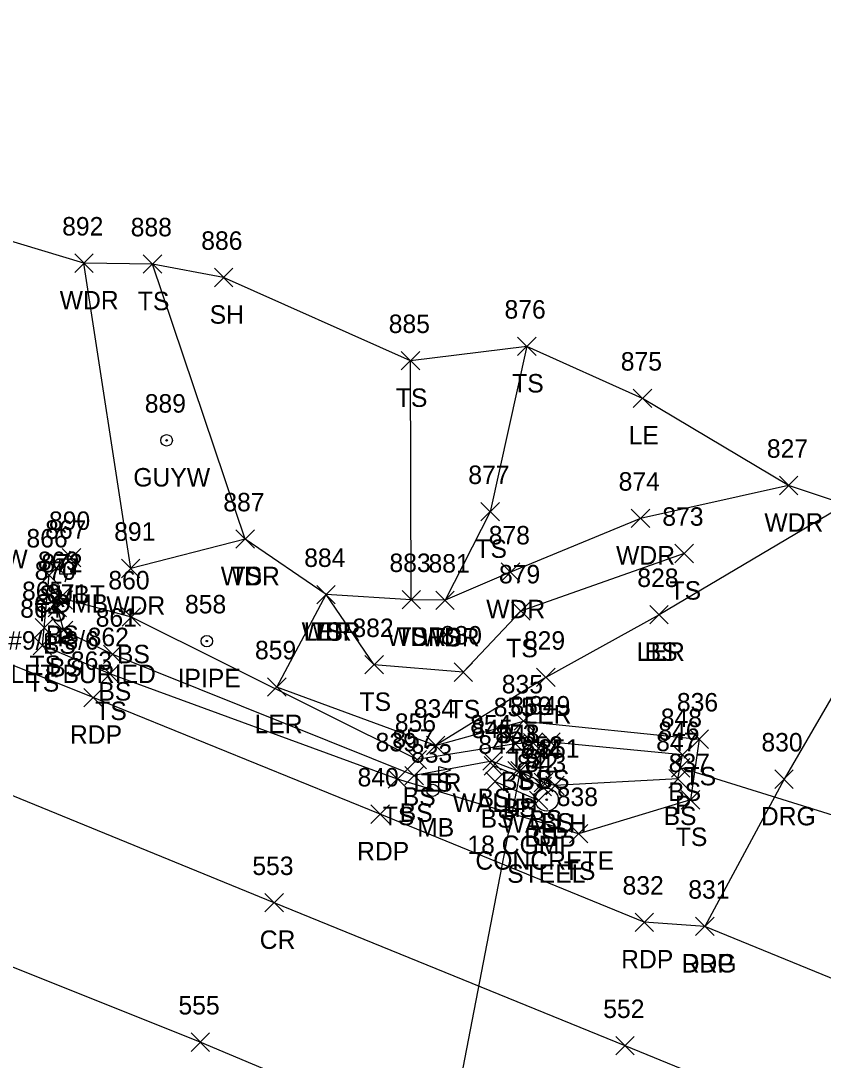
# Model space of a CAD drawing. Extents: x 1599569 to 1610055, y 642560 to 647860.
# Drawn here: x 1603043.9 to 1603130.8, y 647336.2 to 647448.7 of the extents above; entities that cross this region are included whole.
import ezdxf

# ---------------------------------------------------------------- set-up
doc = ezdxf.new("R2010")
doc.units = 0
for name, color, linetype in [('D_A', 7, 'Continuous'), ('D_C', 7, 'Continuous'), ('D_I', 7, 'Continuous'), ('D_TIC', 7, 'Continuous'), ('DCP', 7, 'Continuous'), ('DHW', 7, 'Continuous'), ('L_A', 7, 'Continuous'), ('L_I', 7, 'Continuous'), ('L_TIC', 7, 'Continuous'), ('LARO', 7, 'Continuous'), ('LAWA', 7, 'Continuous'), ('LELB', 7, 'Continuous'), ('LMB', 7, 'Continuous'), ('LSOGP', 7, 'Continuous'), ('M_A', 7, 'Continuous'), ('M_I', 7, 'Continuous'), ('MPIP', 7, 'Continuous'), ('P_A', 7, 'Continuous'), ('P_I', 7, 'Continuous'), ('P_TIC', 7, 'Continuous'), ('PET', 7, 'Continuous'), ('PRC', 7, 'Continuous'), ('R_A', 7, 'Continuous'), ('R_C', 7, 'Continuous'), ('R_I', 7, 'Continuous'), ('R_TIC', 7, 'Continuous'), ('RDG', 7, 'Continuous'), ('RGP', 7, 'Continuous'), ('U_A', 7, 'Continuous'), ('U_C', 7, 'Continuous'), ('U_I', 7, 'Continuous'), ('U_TIC', 7, 'Continuous'), ('UP', 7, 'Continuous'), ('UPGW', 7, 'Continuous')]:
    doc.layers.add(name, color=color, linetype=linetype)

msp = doc.modelspace()

# ---------------------------------------------------------------- linework, layer by layer
at = {"layer": 'D_TIC'}
for points in [[(1603047.45, 647385.01), (1603049.45, 647387.01)], [(1603049.45, 647385.01), (1603047.45, 647387.01)], [(1603094.04, 647367.06), (1603096.04, 647369.06)], [(1603096.04, 647367.06), (1603094.04, 647369.06)], [(1603114.32, 647366.84), (1603116.32, 647368.84)], [(1603116.32, 647366.84), (1603114.32, 647368.84)], [(1603096.94, 647366.51), (1603098.94, 647368.51)], [(1603098.94, 647366.51), (1603096.94, 647368.51)], [(1603099.35, 647364.81), (1603101.35, 647366.81)], [(1603101.35, 647364.81), (1603099.35, 647366.81)]]:
    msp.add_lwpolyline(points, dxfattribs=at)
at = {"layer": 'DCP'}
for points in [[(1603145.08, 647358.57), (1603115.32, 647367.84)], [(1603097.94, 647367.51), (1603085.93, 647305.24)]]:
    msp.add_lwpolyline(points, dxfattribs=at)
at = {"layer": 'DHW'}
msp.add_lwpolyline([(1603100.35, 647365.81), (1603095.04, 647368.06)], dxfattribs=at)
at = {"layer": 'L_TIC'}
for points in [[(1603049.71, 647421.48), (1603051.71, 647423.48)], [(1603051.71, 647421.48), (1603049.71, 647423.48)], [(1603057.13, 647421.39), (1603059.13, 647423.39)], [(1603059.13, 647421.39), (1603057.13, 647423.39)], [(1603064.83, 647419.93), (1603066.83, 647421.93)], [(1603066.83, 647419.93), (1603064.83, 647421.93)], [(1603097.67, 647412.48), (1603099.67, 647414.48)], [(1603099.67, 647412.48), (1603097.67, 647414.48)], [(1603085.07, 647410.92), (1603087.07, 647412.92)], [(1603087.07, 647410.92), (1603085.07, 647412.92)], [(1603110.2, 647406.85), (1603112.2, 647408.85)], [(1603112.2, 647406.85), (1603110.2, 647408.85)], [(1603126.02, 647397.41), (1603128.02, 647399.41)], [(1603128.02, 647397.41), (1603126.02, 647399.41)], [(1603093.69, 647394.57), (1603095.69, 647396.57)], [(1603095.69, 647394.57), (1603093.69, 647396.57)], [(1603109.97, 647393.85), (1603111.97, 647395.85)], [(1603111.97, 647393.85), (1603109.97, 647395.85)], [(1603067.17, 647391.61), (1603069.17, 647393.61)], [(1603069.17, 647391.61), (1603067.17, 647393.61)], [(1603067.17, 647391.61), (1603069.17, 647393.61)], [(1603069.17, 647391.61), (1603067.17, 647393.61)], [(1603114.71, 647390.05), (1603116.71, 647392.05)], [(1603116.71, 647390.05), (1603114.71, 647392.05)], [(1603054.77, 647388.42), (1603056.77, 647390.42)], [(1603056.77, 647388.42), (1603054.77, 647390.42)], [(1603045.94, 647387.7), (1603047.94, 647389.7)], [(1603047.94, 647387.7), (1603045.94, 647389.7)], [(1603095.9, 647388.03), (1603097.9, 647390.03)], [(1603097.9, 647388.03), (1603095.9, 647390.03)], [(1603047.14, 647385.25), (1603049.14, 647387.25)], [(1603049.14, 647385.25), (1603047.14, 647387.25)], [(1603075.92, 647385.59), (1603077.92, 647387.59)], [(1603077.92, 647385.59), (1603075.92, 647387.59)], [(1603075.92, 647385.59), (1603077.92, 647387.59)], [(1603077.92, 647385.59), (1603075.92, 647387.59)], [(1603075.92, 647385.59), (1603077.92, 647387.59)], [(1603077.92, 647385.59), (1603075.92, 647387.59)], [(1603085.15, 647385.04), (1603087.15, 647387.04)], [(1603087.15, 647385.04), (1603085.15, 647387.04)], [(1603085.15, 647385.04), (1603087.15, 647387.04)], [(1603087.15, 647385.04), (1603085.15, 647387.04)], [(1603088.81, 647384.98), (1603090.81, 647386.98)], [(1603090.81, 647384.98), (1603088.81, 647386.98)], [(1603088.81, 647384.98), (1603090.81, 647386.98)], [(1603090.81, 647384.98), (1603088.81, 647386.98)], [(1603046.82, 647384.19), (1603048.82, 647386.19)], [(1603048.82, 647384.19), (1603046.82, 647386.19)], [(1603097.02, 647383.81), (1603099.02, 647385.81)], [(1603099.02, 647383.81), (1603097.02, 647385.81)], [(1603054.84, 647383.16), (1603056.84, 647385.16)], [(1603056.84, 647383.16), (1603054.84, 647385.16)], [(1603111.99, 647383.42), (1603113.99, 647385.42)], [(1603113.99, 647383.42), (1603111.99, 647385.42)], [(1603111.99, 647383.42), (1603113.99, 647385.42)], [(1603113.99, 647383.42), (1603111.99, 647385.42)], [(1603045.41, 647382), (1603047.41, 647384)], [(1603047.41, 647382), (1603045.41, 647384)], [(1603047.5, 647381.72), (1603049.5, 647383.72)], [(1603049.5, 647381.72), (1603047.5, 647383.72)], [(1603047.5, 647381.72), (1603049.5, 647383.72)], [(1603049.5, 647381.72), (1603047.5, 647383.72)], [(1603045.21, 647380.09), (1603047.21, 647382.09)], [(1603047.21, 647380.09), (1603045.21, 647382.09)], [(1603052.82, 647379.12), (1603054.82, 647381.12)], [(1603054.82, 647379.12), (1603052.82, 647381.12)], [(1603081.14, 647378), (1603083.14, 647380)], [(1603083.14, 647378), (1603081.14, 647380)], [(1603052.52, 647377.01), (1603054.52, 647379.01)], [(1603054.52, 647377.01), (1603052.52, 647379.01)], [(1603090.79, 647377.19), (1603092.79, 647379.19)], [(1603092.79, 647377.19), (1603090.79, 647379.19)], [(1603099.72, 647376.63), (1603101.72, 647378.63)], [(1603101.72, 647376.63), (1603099.72, 647378.63)], [(1603070.6, 647375.59), (1603072.6, 647377.59)], [(1603072.6, 647375.59), (1603070.6, 647377.59)], [(1603097.31, 647371.9), (1603099.31, 647373.9)], [(1603099.31, 647371.9), (1603097.31, 647373.9)], [(1603087.79, 647369.26), (1603089.79, 647371.26)], [(1603089.79, 647369.26), (1603087.79, 647371.26)], [(1603087.79, 647369.26), (1603089.79, 647371.26)], [(1603089.79, 647369.26), (1603087.79, 647371.26)], [(1603096.44, 647369.42), (1603098.44, 647371.42)], [(1603098.44, 647369.42), (1603096.44, 647371.42)], [(1603098.32, 647369.56), (1603100.32, 647371.56)], [(1603100.32, 647369.56), (1603098.32, 647371.56)], [(1603100.28, 647369.61), (1603102.28, 647371.61)], [(1603102.28, 647369.61), (1603100.28, 647371.61)], [(1603116.34, 647369.94), (1603118.34, 647371.94)], [(1603118.34, 647369.94), (1603116.34, 647371.94)], [(1603114.53, 647368.25), (1603116.53, 647370.25)], [(1603116.53, 647368.25), (1603114.53, 647370.25)], [(1603085.79, 647367.73), (1603087.79, 647369.73)], [(1603087.79, 647367.73), (1603085.79, 647369.73)], [(1603093.89, 647367.57), (1603095.89, 647369.57)], [(1603095.89, 647367.57), (1603093.89, 647369.57)], [(1603083.66, 647365.62), (1603085.66, 647367.62)], [(1603085.66, 647365.62), (1603083.66, 647367.62)], [(1603085.46, 647365.99), (1603087.46, 647367.99)], [(1603087.46, 647365.99), (1603085.46, 647367.99)], [(1603096.61, 647366.53), (1603098.61, 647368.53)], [(1603098.61, 647366.53), (1603096.61, 647368.53)], [(1603114.03, 647365.64), (1603116.03, 647367.64)], [(1603116.03, 647365.64), (1603114.03, 647367.64)], [(1603114.03, 647365.64), (1603116.03, 647367.64)], [(1603116.03, 647365.64), (1603114.03, 647367.64)], [(1603094.22, 647365.36), (1603096.22, 647367.36)], [(1603096.22, 647365.36), (1603094.22, 647367.36)], [(1603099.47, 647365.25), (1603101.47, 647367.25)], [(1603101.47, 647365.25), (1603099.47, 647367.25)], [(1603100.71, 647364.93), (1603102.71, 647366.93)], [(1603102.71, 647364.93), (1603100.71, 647366.93)], [(1603098.95, 647363.31), (1603100.95, 647365.31)], [(1603100.95, 647363.31), (1603098.95, 647365.31)], [(1603115.39, 647363.37), (1603117.39, 647365.37)], [(1603117.39, 647363.37), (1603115.39, 647365.37)], [(1603103.27, 647359.7), (1603105.27, 647361.7)], [(1603105.27, 647359.7), (1603103.27, 647361.7)]]:
    msp.add_lwpolyline(points, dxfattribs=at)
at = {"layer": 'LARO'}
msp.add_lwpolyline([(1603112.99, 647384.42), (1603100.72, 647377.63), (1603088.79, 647370.26), (1603071.6, 647376.59), (1603076.92, 647386.59)], dxfattribs=at)
at = {"layer": 'LAWA'}
msp.add_lwpolyline([(1603127.02, 647398.41), (1603110.97, 647394.85), (1603096.9, 647389.03), (1603089.81, 647385.98), (1603086.15, 647386.04), (1603076.92, 647386.59), (1603068.17, 647392.61), (1603055.77, 647389.42), (1603050.71, 647422.48)], dxfattribs=at)
at = {"layer": 'LELB'}
for points in [[(1603068.17, 647392.61), (1603058.13, 647422.39)], [(1603098.67, 647413.48), (1603094.69, 647395.57), (1603089.81, 647385.98)], [(1603086.15, 647386.04), (1603086.07, 647411.92)], [(1603133.18, 647396.36), (1603112.99, 647384.42)], [(1603115.71, 647391.05), (1603098.02, 647384.81), (1603091.79, 647378.19), (1603082.14, 647379), (1603076.92, 647386.59)], [(1603088.79, 647370.26), (1603098.31, 647372.9), (1603117.34, 647370.94), (1603116.39, 647364.37), (1603104.27, 647360.7), (1603084.66, 647366.62), (1603053.52, 647378.01), (1603046.21, 647381.09), (1603046.41, 647383), (1603046.94, 647388.7)], [(1603115.03, 647366.64), (1603115.53, 647369.25), (1603101.28, 647370.61), (1603099.32, 647370.56), (1603097.44, 647370.42), (1603086.79, 647368.73), (1603055.84, 647384.16), (1603048.14, 647386.25), (1603047.82, 647385.19), (1603048.5, 647382.72)], [(1603115.03, 647366.64), (1603101.71, 647365.93), (1603100.47, 647366.25), (1603097.61, 647367.53), (1603094.89, 647368.57), (1603086.46, 647366.99), (1603053.82, 647380.12), (1603048.5, 647382.72)], [(1603095.22, 647366.36), (1603099.95, 647364.31)]]:
    msp.add_lwpolyline(points, dxfattribs=at)
at = {"layer": 'LMB'}
for p, q in [((1603089.13, 647368), (1603090.42, 647367.62)), ((1603089.14, 647365.41), (1603089.14, 647368)), ((1603089.14, 647367.1), (1603090.42, 647367.61)), ((1603088.48, 647365.4), (1603088.48, 647365.4))]:
    msp.add_line(p, q, dxfattribs=at)
msp.add_circle((1603088.48, 647365.4), 0.656, dxfattribs=at)
at = {"layer": 'LSOGP'}
msp.add_lwpolyline([(1603245.33, 647331.02), (1603248.92, 647337.89), (1603252.72, 647345.47), (1603220.91, 647358.68), (1603181.83, 647371.46), (1603159.33, 647382.34), (1603155.44, 647382.01), (1603152.78, 647384.38), (1603141.66, 647392.63), (1603133.18, 647396.36), (1603127.02, 647398.41), (1603111.21, 647407.84), (1603098.67, 647413.47), (1603086.07, 647411.91), (1603065.83, 647420.92), (1603058.14, 647422.39), (1603050.71, 647422.48), (1603034.38, 647427.38)], dxfattribs=at)
at = {"layer": 'MPIP'}
for radius in [0.625, 0.0833]:
    msp.add_circle((1603064.01, 647381.56), radius, dxfattribs=at)
at = {"layer": 'P_TIC'}
for points in [[(1603050.7, 647374.44), (1603052.7, 647376.44)], [(1603052.7, 647374.44), (1603050.7, 647376.44)], [(1603081.79, 647361.82), (1603083.79, 647363.82)], [(1603083.79, 647361.82), (1603081.79, 647363.82)], [(1603070.31, 647352.23), (1603072.31, 647354.23)], [(1603072.31, 647352.23), (1603070.31, 647354.23)], [(1603110.39, 647350.11), (1603112.39, 647352.11)], [(1603112.39, 647350.11), (1603110.39, 647352.11)], [(1603116.95, 647349.67), (1603118.95, 647351.67)], [(1603118.95, 647349.67), (1603116.95, 647351.67)], [(1603062.3, 647337.13), (1603064.3, 647339.13)], [(1603064.3, 647337.13), (1603062.3, 647339.13)], [(1603108.3, 647336.75), (1603110.3, 647338.75)], [(1603110.3, 647336.75), (1603108.3, 647338.75)]]:
    msp.add_lwpolyline(points, dxfattribs=at)
at = {"layer": 'PET'}
for points in [[(1603232.97, 647301.58), (1603195.46, 647316.85), (1603162.96, 647330.21), (1603136.43, 647341.31), (1603134.62, 647343.84), (1603117.95, 647350.67), (1603111.39, 647351.11), (1603082.79, 647362.82), (1603051.7, 647375.44), (1603016.01, 647389.74), (1602976.23, 647406.03), (1602937.76, 647421.74), (1602905.04, 647435.16), (1602871.23, 647448.73)], [(1603222.52, 647275.76), (1603183.61, 647291.56), (1603146.92, 647306.71), (1603109.5, 647322.06), (1603103.75, 647321.89), (1603092.3, 647325.95), (1603063.3, 647338.13), (1603037.55, 647348.42), (1603034.26, 647352.47), (1602998.81, 647367.08), (1602958.22, 647383.09), (1602921.43, 647398.55), (1602879.84, 647415.39)]]:
    msp.add_lwpolyline(points, dxfattribs=at)
at = {"layer": 'PRC'}
msp.add_lwpolyline([(1603227.9, 647288.89), (1603189.52, 647304.82), (1603153.33, 647319.71), (1603109.3, 647337.75), (1603071.31, 647353.23), (1603036.99, 647367.27), (1603005.25, 647380.25), (1602963.63, 647397.11), (1602927.12, 647412.15), (1602885.11, 647429.06)], dxfattribs=at)
at = {"layer": 'R_TIC'}
for points in [[(1603125.52, 647365.61), (1603127.52, 647367.61)], [(1603127.52, 647365.61), (1603125.52, 647367.61)], [(1603116.95, 647349.67), (1603118.95, 647351.67)], [(1603118.95, 647349.67), (1603116.95, 647351.67)]]:
    msp.add_lwpolyline(points, dxfattribs=at)
at = {"layer": 'RDG'}
msp.add_lwpolyline([(1603141.66, 647392.63), (1603126.52, 647366.61), (1603117.95, 647350.67)], dxfattribs=at)
at = {"layer": 'RGP'}
msp.add_line((1603100.82, 647364.39), (1603100.82, 647364.39), dxfattribs=at)
for radius in [1.25, 0.0833]:
    msp.add_circle((1603100.82, 647364.39), radius, dxfattribs=at)
at = {"layer": 'U_TIC'}
for points in [[(1603048.36, 647389.6), (1603050.36, 647391.6)], [(1603050.36, 647389.6), (1603048.36, 647391.6)]]:
    msp.add_lwpolyline(points, dxfattribs=at)
at = {"layer": 'UP'}
for p, q in [((1603049.17, 647391.3), (1603048.92, 647390.47)), ((1603048.09, 647388.8), (1603048.09, 647390.47)), ((1603048.09, 647390.47), (1603049.75, 647390.47)), ((1603049.75, 647390.47), (1603049.75, 647388.8)), ((1603048.92, 647389.64), (1603048.92, 647389.64)), ((1603049.75, 647388.8), (1603048.09, 647388.8)), ((1603048.67, 647387.97), (1603048.92, 647388.8))]:
    msp.add_line(p, q, dxfattribs=at)
msp.add_circle((1603048.92, 647389.64), 0.833, dxfattribs=at)
at = {"layer": 'UPGW'}
for radius in [0.625, 0.0833]:
    msp.add_circle((1603059.66, 647403.3), radius, dxfattribs=at)

# ---------------------------------------------------------------- texts
at = {"layer": 'D_A'}
for s, p in [('P', (1603047.83, 647381.01)), ('WALLH', (1603090.63, 647363.06)), ('P', (1603097.32, 647362.51)), ('P', (1603114.7, 647362.84)), ('WALLH', (1603095.94, 647360.81))]:
    msp.add_text(s, height=2, dxfattribs=at).set_placement(p)
at = {"layer": 'D_C'}
for s, p in [('OUTLET BURIED', (1603037.09, 647377.01)), ('18 CGMP', (1603092.23, 647358.51)), ('CONCRETE', (1603093.1, 647356.81))]:
    msp.add_text(s, height=2, dxfattribs=at).set_placement(p)
at = {"layer": 'D_I'}
for s, p in [('872', (1603046.09, 647389.01)), ('845', (1603092.67, 647371.06)), ('548', (1603095.58, 647370.51)), ('846', (1603112.9, 647370.84)), ('844', (1603097.98, 647368.81))]:
    msp.add_text(s, height=2, dxfattribs=at).set_placement(p)
at = {"layer": 'L_A'}
for s, p in [('WDR', (1603048.08, 647417.48)), ('TS', (1603056.54, 647417.39)), ('SH', (1603064.32, 647415.93)), ('TS', (1603097.08, 647408.48)), ('TS', (1603084.48, 647406.92)), ('LE', (1603109.69, 647402.85)), ('WDR', (1603124.39, 647393.41)), ('TS', (1603093.1, 647390.57)), ('WDR', (1603108.33, 647389.85)), ('WDR', (1603065.53, 647387.61)), ('TS', (1603066.58, 647387.61)), ('TS', (1603114.12, 647386.05)), ('TS', (1603045.35, 647383.7)), ('WDR', (1603053.13, 647384.42)), ('WDR', (1603094.27, 647384.03)), ('WDR', (1603074.28, 647381.59)), ('LER', (1603074.5, 647381.59)), ('TS', (1603075.33, 647381.59)), ('BS', (1603046.26, 647380.19)), ('BS', (1603046.58, 647381.25)), ('WDR', (1603083.51, 647381.04)), ('TS', (1603084.56, 647381.04)), ('WDR', (1603087.17, 647380.98)), ('TS', (1603088.22, 647380.98)), ('BS', (1603054.28, 647379.16)), ('TS', (1603096.43, 647379.81)), ('LER', (1603110.57, 647379.42)), ('BS', (1603111.43, 647379.42)), ('TS', (1603044.82, 647378)), ('BS', (1603046.94, 647377.72)), ('BS', (1603046.94, 647377.72)), ('TS', (1603044.62, 647376.09)), ('BS', (1603052.27, 647375.12)), ('TS', (1603080.55, 647374)), ('TS', (1603051.93, 647373.01)), ('TS', (1603090.2, 647373.19)), ('LER', (1603098.3, 647372.63)), ('LER', (1603069.18, 647371.59)), ('TS', (1603096.72, 647367.9)), ('BS', (1603097.77, 647365.56)), ('BS', (1603099.72, 647365.61)), ('TS', (1603115.75, 647365.94)), ('LER', (1603086.38, 647365.26)), ('TS', (1603087.2, 647365.26)), ('BS', (1603095.88, 647365.42)), ('BS', (1603085.23, 647363.73)), ('BS', (1603093.33, 647363.57)), ('BS', (1603113.97, 647364.25)), ('BS', (1603096.05, 647362.53)), ('TS', (1603083.07, 647361.62)), ('BS', (1603084.9, 647361.99)), ('BS', (1603093.66, 647361.36)), ('BS', (1603098.92, 647361.25)), ('BS', (1603113.47, 647361.64)), ('BS', (1603113.47, 647361.64)), ('MB', (1603086.79, 647360.4)), ('BS', (1603100.15, 647360.93)), ('BS', (1603098.39, 647359.31)), ('TS', (1603114.8, 647359.37)), ('TS', (1603102.68, 647355.7))]:
    msp.add_text(s, height=2, dxfattribs=at).set_placement(p)
at = {"layer": 'L_I'}
for s, p in [('892', (1603048.35, 647425.48)), ('888', (1603055.77, 647425.39)), ('886', (1603063.41, 647423.93)), ('876', (1603096.25, 647416.48)), ('885', (1603083.71, 647414.92)), ('875', (1603108.84, 647410.85)), ('827', (1603124.66, 647401.41)), ('877', (1603092.33, 647398.57)), ('874', (1603108.61, 647397.85)), ('887', (1603065.8, 647395.61)), ('887', (1603065.8, 647395.61)), ('873', (1603113.34, 647394.05)), ('866', (1603044.48, 647391.7)), ('891', (1603053.98, 647392.42)), ('878', (1603094.54, 647392.03)), ('869', (1603045.72, 647389.25)), ('884', (1603074.56, 647389.59)), ('884', (1603074.56, 647389.59)), ('884', (1603074.56, 647389.59)), ('870', (1603045.37, 647388.19)), ('883', (1603083.79, 647389.04)), ('883', (1603083.79, 647389.04)), ('881', (1603088.02, 647388.98)), ('881', (1603088.02, 647388.98)), ('860', (1603053.35, 647387.16)), ('879', (1603095.65, 647387.81)), ('828', (1603110.63, 647387.42)), ('828', (1603110.63, 647387.42)), ('865', (1603044, 647386)), ('871', (1603046.7, 647385.72)), ('871', (1603046.7, 647385.72)), ('864', (1603043.8, 647384.09)), ('861', (1603051.98, 647383.12)), ('882', (1603079.78, 647382)), ('862', (1603051.11, 647381.01)), ('880', (1603089.34, 647381.19)), ('829', (1603098.35, 647380.63)), ('859', (1603069.23, 647379.59)), ('835', (1603095.95, 647375.9)), ('855', (1603095.08, 647373.42)), ('850', (1603096.88, 647373.56)), ('849', (1603098.91, 647373.61)), ('836', (1603114.92, 647373.94)), ('834', (1603086.43, 647373.26)), ('834', (1603086.43, 647373.26)), ('856', (1603084.37, 647371.73)), ('854', (1603092.53, 647371.57)), ('848', (1603113.17, 647372.25)), ('853', (1603095.25, 647370.53)), ('839', (1603082.29, 647369.62)), ('857', (1603084.1, 647369.99)), ('841', (1603093.42, 647369.36)), ('852', (1603098.11, 647369.25)), ('851', (1603099.91, 647368.93)), ('847', (1603112.67, 647369.64)), ('847', (1603112.67, 647369.64)), ('833', (1603086.12, 647368.4)), ('842', (1603097.59, 647367.31)), ('837', (1603114.03, 647367.37)), ('838', (1603101.91, 647363.7))]:
    msp.add_text(s, height=2, dxfattribs=at).set_placement(p)
at = {"layer": 'M_A'}
msp.add_text('IPIPE', height=2, dxfattribs=at).set_placement((1603060.85, 647376.56))
at = {"layer": 'M_I'}
msp.add_text('858', height=2, dxfattribs=at).set_placement((1603061.65, 647384.56))
at = {"layer": 'P_A'}
for s, p in [('RDP', (1603049.19, 647370.44)), ('RDP', (1603080.28, 647357.82)), ('CR', (1603069.74, 647348.23)), ('RDP', (1603108.88, 647346.11)), ('RDP', (1603115.43, 647345.67))]:
    msp.add_text(s, height=2, dxfattribs=at).set_placement(p)
at = {"layer": 'P_I'}
for s, p in [('863', (1603049.29, 647378.44)), ('840', (1603080.34, 647365.82)), ('553', (1603068.94, 647356.23)), ('832', (1603109.03, 647354.11)), ('831', (1603116.15, 647353.67)), ('555', (1603060.94, 647341.13)), ('552', (1603106.94, 647340.75))]:
    msp.add_text(s, height=2, dxfattribs=at).set_placement(p)
at = {"layer": 'R_A'}
for s, p in [('DRG', (1603124.01, 647361.61)), ('GP', (1603099.26, 647359.39)), ('DRG', (1603115.43, 647345.67))]:
    msp.add_text(s, height=2, dxfattribs=at).set_placement(p)
at = {"layer": 'R_C'}
msp.add_text('STEEL', height=2, dxfattribs=at).set_placement((1603096.54, 647355.39))
at = {"layer": 'R_I'}
for s, p in [('830', (1603124.07, 647369.61)), ('843', (1603098.46, 647367.39)), ('831', (1603116.15, 647353.67))]:
    msp.add_text(s, height=2, dxfattribs=at).set_placement(p)
at = {"layer": 'U_A'}
for s, p in [('GUYW', (1603056.05, 647398.3)), ('GUYW', (1603036.29, 647389.45)), ('COMB', (1603045.3, 647384.64)), ('SUBT', (1603045.86, 647385.6))]:
    msp.add_text(s, height=2, dxfattribs=at).set_placement(p)
at = {"layer": 'U_C'}
msp.add_text('#9/1-8/6', height=2, dxfattribs=at).set_placement((1603042.5, 647380.64))
at = {"layer": 'U_I'}
for s, p in [('889', (1603057.29, 647406.3)), ('867', (1603046.51, 647392.64)), ('890', (1603046.92, 647393.6))]:
    msp.add_text(s, height=2, dxfattribs=at).set_placement(p)

doc.saveas('drawing.dxf')
